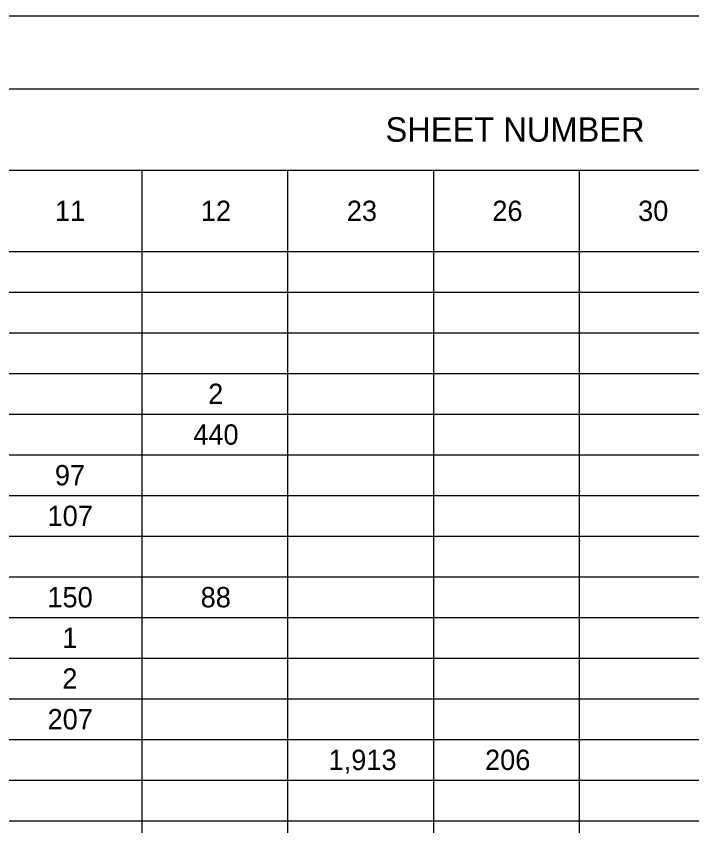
# Model space of a CAD drawing. Extents: x 0 to 34, y 0 to 22.
# Drawn here: x 4.65 to 9.31, y 16.43 to 22 of the extents above; entities that cross this region are included whole.
import ezdxf

# ---------------------------------------------------------------- set-up
doc = ezdxf.new("R2010")
doc.units = 0
for name, color, linetype in [('SH_Border', 7, 'Continuous'), ('SH_Cut_Line', 7, 'Continuous'), ('SH_Data', 7, 'Continuous'), ('SH_Text', 7, 'Continuous')]:
    doc.layers.add(name, color=color, linetype=linetype)

msp = doc.modelspace()

# ---------------------------------------------------------------- linework, layer by layer
at = {"layer": 'SH_Border'}
msp.add_lwpolyline([(1.5, 21.5), (33.5, 21.5), (33.5, 0.5), (1.5, 0.5)], close=True, dxfattribs=at)
at = {"layer": 'SH_Cut_Line'}
msp.add_lwpolyline([(0, 0), (34, 0), (34, 22), (0, 22)], close=True, dxfattribs=at)
at = {"layer": 'SH_Data'}
for p, q in [((1.5, 21.5), (32.0036, 21.5)), ((1.5, 20.94), (15.5659, 20.94)), ((5.5188, 20.94), (5.5188, 0.5)), ((6.5235, 20.94), (6.5235, 0.5)), ((7.5282, 20.94), (7.5282, 0.5)), ((8.5329, 20.94), (8.5329, 0.5)), ((1.5, 20.38), (32.0036, 20.38)), ((1.5, 20.1), (32.0036, 20.1)), ((1.5, 19.82), (32.0036, 19.82)), ((1.5, 19.54), (32.0036, 19.54)), ((1.5, 19.26), (32.0036, 19.26)), ((1.5, 18.98), (32.0036, 18.98)), ((1.5, 18.7), (32.0036, 18.7)), ((1.5, 18.42), (32.0036, 18.42)), ((1.5, 18.14), (32.0036, 18.14)), ((1.5, 17.86), (32.0036, 17.86)), ((1.5, 17.58), (32.0036, 17.58)), ((1.5, 17.3), (32.0036, 17.3)), ((1.5, 17.02), (32.0036, 17.02)), ((1.5, 16.74), (32.0036, 16.74)), ((1.5, 16.46), (32.0036, 16.46))]:
    msp.add_line(p, q, dxfattribs=at)

# ---------------------------------------------------------------- texts
at = {"layer": 'SH_Text'}
for s, height, p in [('SHEET NUMBER', 0.168, (7.1981, 21.136)), ('11', 0.14, (4.9213, 20.59)), ('12', 0.14, (5.9261, 20.59)), ('23', 0.14, (6.9314, 20.59)), ('26', 0.14, (7.9339, 20.59)), ('30', 0.14, (8.9382, 20.59)), ('2', 0.14, (5.9764, 19.33)), ('440', 0.14, (5.8738, 19.05)), ('97', 0.14, (4.9205, 18.77)), ('107', 0.14, (4.8702, 18.49)), ('150', 0.14, (4.8691, 17.93)), ('88', 0.14, (5.9247, 17.93)), ('1', 0.14, (4.9716, 17.65)), ('2', 0.14, (4.9717, 17.37)), ('207', 0.14, (4.8702, 17.09)), ('1,913', 0.14, (6.806, 16.81)), ('206', 0.14, (7.8837, 16.81))]:
    msp.add_text(s, height=height, dxfattribs=at).set_placement(p)

doc.saveas('drawing.dxf')
